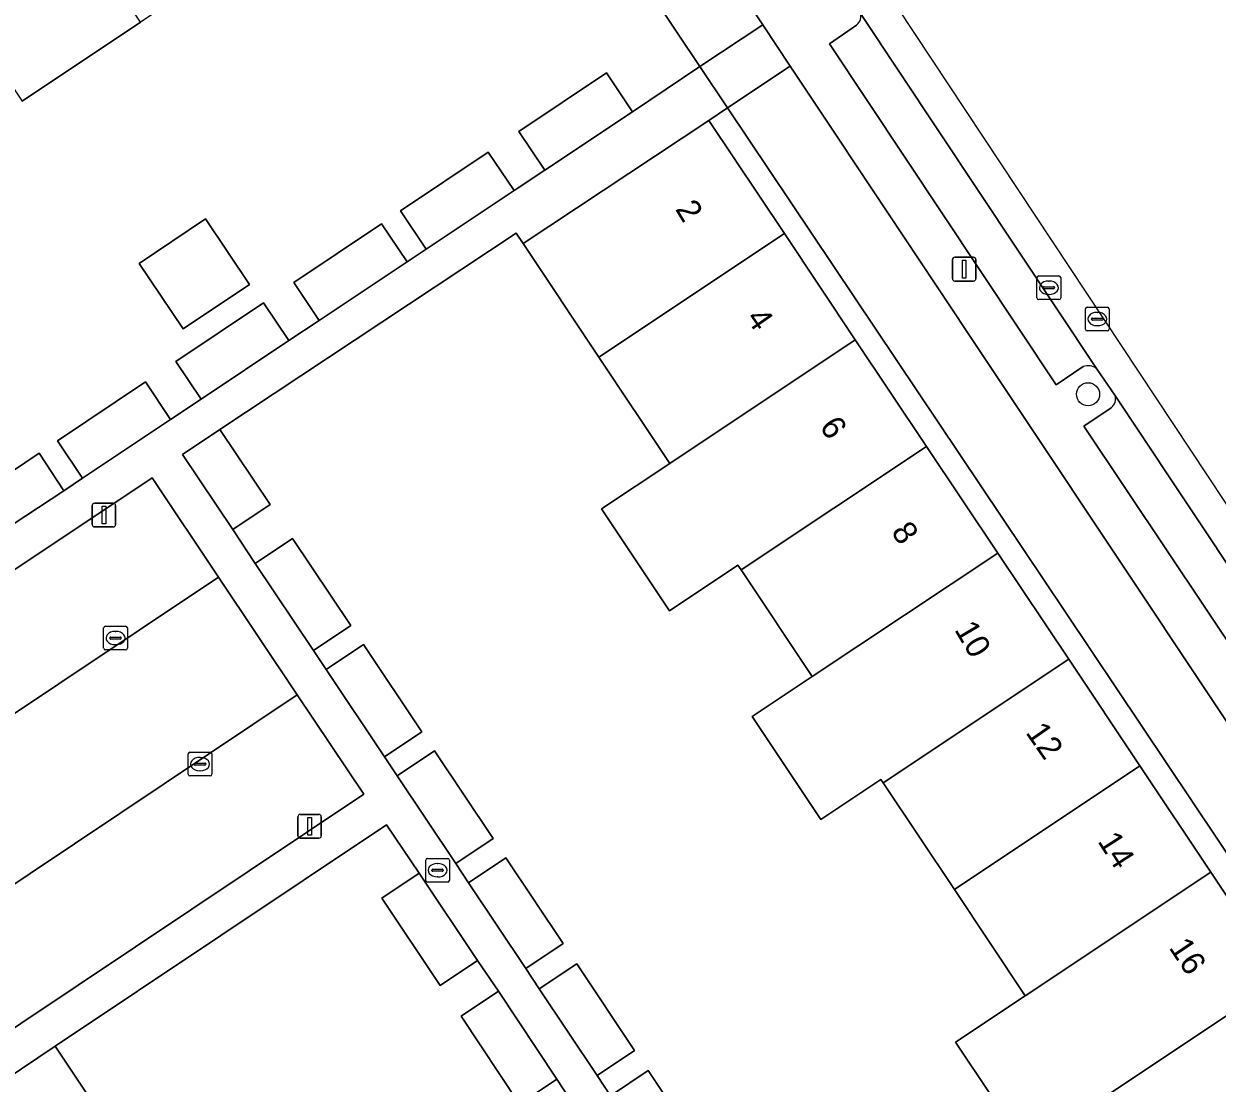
# Model space of a CAD drawing. Extents: x 158352 to 159489, y 383828 to 384603.
# Drawn here: x 158853 to 158903.3, y 384412.1 to 384456.8 of the extents above; entities that cross this region are included whole.
import ezdxf

# ---------------------------------------------------------------- set-up
doc = ezdxf.new("R2010")
doc.units = 0
for name, color, linetype in [('IMGEO_Boom', 7, 'Continuous'), ('IMGEO_Erf', 7, 'Continuous'), ('IMGEO_Kolk', 7, 'Continuous'), ('IMGEO_Lichtmast', 7, 'Continuous'), ('IMGEO_Pand', 7, 'Continuous'), ('IMGEO_Pand_nummerreeks', 7, 'Continuous'), ('IMGEO_Parkeervlak_open', 7, 'Continuous'), ('IMGEO_Rijbaan_lokaal_gesloten', 7, 'Continuous'), ('IMGEO_Rijbaan_lokaal_open', 7, 'Continuous'), ('IMGEO_Rioolput', 7, 'Continuous'), ('IMGEO_Voetpad_open', 7, 'Continuous')]:
    doc.layers.add(name, color=color, linetype=linetype)

msp = doc.modelspace()

# ---------------------------------------------------------------- linework, layer by layer
at = {"layer": 'IMGEO_Boom'}
msp.add_circle((158897.897, 384441.16), 0.489, dxfattribs=at)
at = {"layer": 'IMGEO_Erf'}
for points in [[(158871.439, 384475.884), (158869.53, 384478.817), (158866.797, 384476.999), (158881.542, 384454.976), (158884.184, 384456.734)], [(158899.598, 384433.573), (158885.345, 384454.99), (158882.708, 384453.235), (158896.943, 384431.973), (158958.047, 384340.708), (158960.345, 384342.297)], [(158857.909, 384446.679), (158860.705, 384448.554), (158862.558, 384445.789), (158859.762, 384443.914)]]:
    msp.add_lwpolyline(points, close=True, dxfattribs=at)
for points in [[(158849.97, 384436.184), (158853.689, 384438.677), (158854.728, 384437.092), (158855.524, 384437.619), (158854.466, 384439.198), (158858.167, 384441.679), (158859.227, 384440.097), (158860.515, 384440.96), (158859.454, 384442.542), (158863.15, 384445.02), (158864.218, 384443.427), (158865.492, 384444.275), (158864.421, 384445.872), (158868.117, 384448.35), (158869.195, 384446.742), (158870.003, 384447.28), (158868.923, 384448.89), (158872.619, 384451.368), (158873.706, 384449.747), (158874.996, 384450.606), (158873.906, 384452.231), (158877.603, 384454.709), (158878.7, 384453.073), (158881.542, 384454.976), (158866.797, 384476.999)], [(158848.053, 384460.87), (158853.047, 384464.192), (158857.548, 384467.185), (158862.533, 384470.501), (158867.746, 384473.968), (158872.617, 384466.647), (158872.513, 384466.577), (158874.416, 384463.732), (158869.334, 384460.333), (158869.095, 384460.69), (158864.119, 384457.362), (158862.455, 384459.85), (158857.962, 384456.845), (158852.977, 384453.51)], [(158958.047, 384340.708), (158896.943, 384431.973), (158882.708, 384453.235), (158881.915, 384452.704), (158885.098, 384447.937), (158888.089, 384443.457), (158891.089, 384438.962), (158894.09, 384434.468), (158897.081, 384429.988), (158900.082, 384425.492), (158903.072, 384421.013), (158906.071, 384416.517), (158909.059, 384412.037)], [(158895.312, 384409.35), (158892.313, 384413.844), (158895.254, 384415.804), (158892.264, 384420.284), (158889.263, 384424.78), (158889.165, 384424.926), (158886.635, 384423.238), (158883.741, 384427.573), (158886.273, 384429.26), (158883.272, 384433.755), (158883.137, 384433.958), (158880.26, 384432.037), (158877.396, 384436.329), (158880.272, 384438.249), (158877.282, 384442.729), (158874.09, 384447.51), (158873.799, 384447.946), (158861.31, 384439.679), (158863.428, 384436.513), (158861.849, 384435.456), (158862.793, 384434.029), (158864.373, 384435.085), (158866.83, 384431.412), (158865.251, 384430.356), (158865.783, 384429.557), (158867.363, 384430.613), (158869.819, 384426.934), (158868.239, 384425.879), (158868.777, 384425.077), (158870.356, 384426.129), (158872.827, 384422.43), (158871.247, 384421.375), (158871.788, 384420.567), (158873.366, 384421.619), (158875.777, 384418.007), (158874.196, 384416.953), (158874.77, 384416.094), (158876.351, 384417.147), (158878.786, 384413.498), (158877.203, 384412.443), (158877.767, 384411.592), (158879.351, 384412.652), (158881.773, 384409.023)], [(158876.048, 384411.482), (158875.511, 384412.288), (158873.932, 384411.231), (158871.473, 384414.946), (158873.052, 384416.003), (158872.17, 384417.289), (158870.591, 384416.233), (158868.129, 384419.915), (158869.709, 384420.971), (158868.332, 384423.007), (158854.372, 384413.675), (158857.87, 384408.431)]]:
    msp.add_lwpolyline(points, dxfattribs=at)
at = {"layer": 'IMGEO_Kolk'}
for p, q in [((158895.745, 384445.227), (158895.745, 384446.079)), ((158895.82, 384446.153), (158896.672, 384446.153)), ((158896.746, 384446.079), (158896.746, 384445.227)), ((158896.004, 384445.647), (158896.004, 384445.659)), ((158896.442, 384445.61), (158896.044, 384445.61)), ((158896.047, 384445.696), (158896.445, 384445.696)), ((158896.233, 384445.933), (158896.258, 384445.933)), ((158896.488, 384445.659), (158896.488, 384445.647)), ((158896.672, 384445.153), (158895.82, 384445.153)), ((158896.256, 384445.373), (158896.231, 384445.373)), ((158856.409, 384430.46), (158856.409, 384431.312)), ((158856.484, 384431.386), (158857.336, 384431.386)), ((158856.897, 384431.166), (158856.922, 384431.166)), ((158857.41, 384431.312), (158857.41, 384430.46)), ((158856.668, 384430.88), (158856.668, 384430.892)), ((158857.106, 384430.843), (158856.708, 384430.843)), ((158856.711, 384430.929), (158857.109, 384430.929)), ((158856.92, 384430.606), (158856.895, 384430.606)), ((158857.152, 384430.892), (158857.152, 384430.88)), ((158857.336, 384430.386), (158856.484, 384430.386)), ((158859.972, 384425.147), (158859.972, 384425.999)), ((158860.047, 384426.073), (158860.899, 384426.073)), ((158860.973, 384425.999), (158860.973, 384425.147)), ((158860.231, 384425.567), (158860.231, 384425.579)), ((158860.669, 384425.53), (158860.271, 384425.53)), ((158860.274, 384425.616), (158860.672, 384425.616)), ((158860.46, 384425.853), (158860.485, 384425.853)), ((158860.715, 384425.579), (158860.715, 384425.567)), ((158860.899, 384425.073), (158860.047, 384425.073)), ((158860.483, 384425.293), (158860.458, 384425.293)), ((158869.981, 384420.671), (158869.981, 384421.523)), ((158870.056, 384421.597), (158870.908, 384421.597)), ((158870.982, 384421.523), (158870.982, 384420.671)), ((158870.24, 384421.091), (158870.24, 384421.103)), ((158870.678, 384421.054), (158870.28, 384421.054)), ((158870.283, 384421.14), (158870.681, 384421.14)), ((158870.469, 384421.377), (158870.494, 384421.377)), ((158870.724, 384421.103), (158870.724, 384421.091)), ((158870.908, 384420.597), (158870.056, 384420.597)), ((158870.492, 384420.817), (158870.467, 384420.817))]:
    msp.add_line(p, q, dxfattribs=at)
for points in [[(158895.745, 384445.227), (158895.745, 384446.079)], [(158895.82, 384446.153), (158896.672, 384446.153)], [(158896.746, 384446.079), (158896.746, 384445.227)], [(158896.672, 384445.153), (158895.82, 384445.153)], [(158856.409, 384430.46), (158856.409, 384431.312)], [(158856.484, 384431.386), (158857.336, 384431.386)], [(158857.41, 384431.312), (158857.41, 384430.46)], [(158857.336, 384430.386), (158856.484, 384430.386)], [(158859.972, 384425.147), (158859.972, 384425.999)], [(158860.047, 384426.073), (158860.899, 384426.073)], [(158860.973, 384425.999), (158860.973, 384425.147)], [(158860.899, 384425.073), (158860.047, 384425.073)], [(158869.981, 384420.671), (158869.981, 384421.523)], [(158870.056, 384421.597), (158870.908, 384421.597)], [(158870.982, 384421.523), (158870.982, 384420.671)], [(158870.908, 384420.597), (158870.056, 384420.597)]]:
    msp.add_lwpolyline(points, dxfattribs=at)
for centre, radius, start, end in [((158895.822, 384446.077), 0.0765, 91.552, 178.448), ((158895.822, 384446.077), 0.0765, 91.552, 178.448), ((158896.67, 384446.077), 0.0765, 1.552, 88.448), ((158896.67, 384446.077), 0.0765, 1.552, 88.448), ((158896.044, 384445.656), 0.0403, 85.8775, 175.7526), ((158896.041, 384445.646), 0.0366, 178.938, 274.7102), ((158896.445, 384445.653), 0.043, 264.8664, 352.4533), ((158896.449, 384445.658), 0.0386, 1.7309, 96.639), ((158895.822, 384445.229), 0.0765, 181.552, 268.448), ((158895.822, 384445.229), 0.0765, 181.552, 268.448), ((158896.67, 384445.229), 0.0765, 271.552, 358.448), ((158896.67, 384445.229), 0.0765, 271.552, 358.448), ((158856.486, 384431.31), 0.0765, 91.552, 178.448), ((158856.486, 384431.31), 0.0765, 91.552, 178.448), ((158857.334, 384431.31), 0.0765, 1.552, 88.448), ((158857.334, 384431.31), 0.0765, 1.552, 88.448), ((158856.486, 384430.462), 0.0765, 181.552, 268.448), ((158856.486, 384430.462), 0.0765, 181.552, 268.448), ((158856.708, 384430.889), 0.0403, 85.8775, 175.7526), ((158856.705, 384430.879), 0.0366, 178.938, 274.7102), ((158857.109, 384430.886), 0.043, 264.8664, 352.4533), ((158857.113, 384430.891), 0.0386, 1.7309, 96.639), ((158857.334, 384430.462), 0.0765, 271.552, 358.448), ((158857.334, 384430.462), 0.0765, 271.552, 358.448), ((158860.049, 384425.997), 0.0765, 91.552, 178.448), ((158860.049, 384425.997), 0.0765, 91.552, 178.448), ((158860.897, 384425.997), 0.0765, 1.552, 88.448), ((158860.897, 384425.997), 0.0765, 1.552, 88.448), ((158860.271, 384425.576), 0.0403, 85.8775, 175.7526), ((158860.268, 384425.566), 0.0366, 178.938, 274.7102), ((158860.672, 384425.573), 0.043, 264.8664, 352.4533), ((158860.676, 384425.578), 0.0386, 1.7309, 96.639), ((158860.049, 384425.149), 0.0765, 181.552, 268.448), ((158860.049, 384425.149), 0.0765, 181.552, 268.448), ((158860.897, 384425.149), 0.0765, 271.552, 358.448), ((158860.897, 384425.149), 0.0765, 271.552, 358.448), ((158870.058, 384421.521), 0.0765, 91.552, 178.448), ((158870.058, 384421.521), 0.0765, 91.552, 178.448), ((158870.906, 384421.521), 0.0765, 1.552, 88.448), ((158870.906, 384421.521), 0.0765, 1.552, 88.448), ((158870.28, 384421.1), 0.0403, 85.8775, 175.7526), ((158870.277, 384421.09), 0.0366, 178.938, 274.7102), ((158870.681, 384421.097), 0.043, 264.8664, 352.4533), ((158870.685, 384421.102), 0.0386, 1.7309, 96.639), ((158870.058, 384420.673), 0.0765, 181.552, 268.448), ((158870.058, 384420.673), 0.0765, 181.552, 268.448), ((158870.906, 384420.673), 0.0765, 271.552, 358.448), ((158870.906, 384420.673), 0.0765, 271.552, 358.448)]:
    msp.add_arc(centre, radius, start, end, dxfattribs=at)
for centre, major_axis, ratio, start_param, end_param in [((158896.232, 384445.653), (-0.387, 0.002), 0.722429, 4.712389, 7.853982), ((158896.257, 384445.653), (-0.39, 0.002), 0.717154, 1.570796, 4.712389), ((158856.896, 384430.886), (-0.387, 0.002), 0.722429, 4.712389, 7.853982), ((158856.921, 384430.886), (-0.39, 0.002), 0.717154, 1.570796, 4.712389), ((158860.459, 384425.573), (-0.387, 0.002), 0.722429, 4.712389, 7.853982), ((158860.484, 384425.573), (-0.39, 0.002), 0.717154, 1.570796, 4.712389), ((158870.468, 384421.097), (-0.387, 0.002), 0.722429, 4.712389, 7.853982), ((158870.493, 384421.097), (-0.39, 0.002), 0.717154, 1.570796, 4.712389)]:
    msp.add_ellipse(centre, major_axis=major_axis, ratio=ratio, start_param=start_param, end_param=end_param, dxfattribs=at)
at = {"layer": 'IMGEO_Lichtmast'}
for p, q in [((158892.183, 384446.036), (158892.183, 384446.836)), ((158892.183, 384446.836), (158892.183, 384446.036)), ((158892.283, 384446.936), (158893.073, 384446.936)), ((158893.073, 384446.936), (158892.283, 384446.936)), ((158893.173, 384446.836), (158893.173, 384446.036)), ((158893.173, 384446.036), (158893.173, 384446.836)), ((158893.073, 384445.936), (158892.283, 384445.936)), ((158892.283, 384445.936), (158893.073, 384445.936)), ((158856.024, 384436.571), (158856.814, 384436.571)), ((158856.814, 384436.571), (158856.024, 384436.571)), ((158855.924, 384435.671), (158855.924, 384436.471)), ((158855.924, 384436.471), (158855.924, 384435.671)), ((158856.914, 384436.471), (158856.914, 384435.671)), ((158856.914, 384435.671), (158856.914, 384436.471)), ((158856.814, 384435.571), (158856.024, 384435.571)), ((158856.024, 384435.571), (158856.814, 384435.571)), ((158864.692, 384423.45), (158865.482, 384423.45)), ((158865.482, 384423.45), (158864.692, 384423.45)), ((158864.592, 384422.55), (158864.592, 384423.35)), ((158864.592, 384423.35), (158864.592, 384422.55)), ((158865.582, 384423.35), (158865.582, 384422.55)), ((158865.582, 384422.55), (158865.582, 384423.35)), ((158865.482, 384422.45), (158864.692, 384422.45)), ((158864.692, 384422.45), (158865.482, 384422.45))]:
    msp.add_line(p, q, dxfattribs=at)
for points in [[(158892.603, 384446.811), (158892.753, 384446.811), (158892.753, 384446.061), (158892.603, 384446.061), (158892.603, 384446.811)], [(158856.344, 384436.446), (158856.494, 384436.446), (158856.494, 384435.696), (158856.344, 384435.696), (158856.344, 384436.446)], [(158865.012, 384423.325), (158865.162, 384423.325), (158865.162, 384422.575), (158865.012, 384422.575), (158865.012, 384423.325)]]:
    msp.add_lwpolyline(points, dxfattribs=at)
for centre, start, end in [((158892.283, 384446.836), 90, 180), ((158892.283, 384446.836), 90, 180), ((158893.073, 384446.836), 0, 90), ((158893.073, 384446.836), 360, 90), ((158892.283, 384446.036), 180, 270), ((158892.283, 384446.036), 180, 270), ((158893.073, 384446.036), 270, 0), ((158893.073, 384446.036), 270, 0), ((158856.024, 384436.471), 90, 180), ((158856.024, 384436.471), 90, 180), ((158856.814, 384436.471), 0, 90), ((158856.814, 384436.471), 360, 90), ((158856.024, 384435.671), 180, 270), ((158856.024, 384435.671), 180, 270), ((158856.814, 384435.671), 270, 0), ((158856.814, 384435.671), 270, 0), ((158864.692, 384423.35), 90, 180), ((158864.692, 384423.35), 90, 180), ((158865.482, 384423.35), 0, 90), ((158865.482, 384423.35), 360, 90), ((158864.692, 384422.55), 180, 270), ((158864.692, 384422.55), 180, 270), ((158865.482, 384422.55), 270, 0), ((158865.482, 384422.55), 270, 0)]:
    msp.add_arc(centre, 0.1, start, end, dxfattribs=at)
at = {"layer": 'IMGEO_Pand'}
for points in [[(158853.047, 384464.192), (158848.053, 384460.87), (158852.977, 384453.51), (158857.962, 384456.845)], [(158874.996, 384450.606), (158878.7, 384453.073), (158877.603, 384454.709), (158873.906, 384452.231)], [(158885.098, 384447.937), (158881.915, 384452.704), (158874.09, 384447.51), (158877.282, 384442.729)], [(158870.003, 384447.28), (158873.706, 384449.747), (158872.619, 384451.368), (158868.923, 384448.89)], [(158857.909, 384446.679), (158859.762, 384443.914), (158862.558, 384445.789), (158860.705, 384448.554)], [(158865.492, 384444.275), (158869.195, 384446.742), (158868.117, 384448.35), (158864.421, 384445.872)], [(158885.098, 384447.937), (158877.282, 384442.729), (158880.272, 384438.249), (158888.089, 384443.457)], [(158864.218, 384443.427), (158863.15, 384445.02), (158859.454, 384442.542), (158860.515, 384440.96)], [(158891.089, 384438.962), (158888.089, 384443.457), (158880.272, 384438.249), (158877.396, 384436.329), (158880.26, 384432.037), (158883.137, 384433.958), (158883.272, 384433.755)], [(158855.524, 384437.619), (158859.227, 384440.097), (158858.167, 384441.679), (158854.466, 384439.198)], [(158861.31, 384439.679), (158859.731, 384438.622), (158861.849, 384435.456), (158863.428, 384436.513)], [(158850.984, 384434.637), (158854.728, 384437.092), (158853.689, 384438.677), (158849.97, 384436.184)], [(158891.089, 384438.962), (158883.272, 384433.755), (158886.273, 384429.26), (158894.09, 384434.468)], [(158865.251, 384430.356), (158866.83, 384431.412), (158864.373, 384435.085), (158862.793, 384434.029)], [(158897.081, 384429.988), (158894.09, 384434.468), (158886.273, 384429.26), (158883.741, 384427.573), (158886.635, 384423.238), (158889.165, 384424.926), (158889.263, 384424.78)], [(158865.783, 384429.557), (158868.239, 384425.879), (158869.819, 384426.934), (158867.363, 384430.613)], [(158900.082, 384425.492), (158897.081, 384429.988), (158889.263, 384424.78), (158892.264, 384420.284)], [(158868.777, 384425.077), (158871.247, 384421.375), (158872.827, 384422.43), (158870.356, 384426.129)], [(158900.082, 384425.492), (158892.264, 384420.284), (158895.254, 384415.804), (158903.072, 384421.013)], [(158871.788, 384420.567), (158874.196, 384416.953), (158875.777, 384418.007), (158873.366, 384421.619)], [(158869.709, 384420.971), (158868.129, 384419.915), (158870.591, 384416.233), (158872.17, 384417.289)], [(158906.071, 384416.517), (158903.072, 384421.013), (158895.254, 384415.804), (158892.313, 384413.844), (158895.312, 384409.35), (158898.254, 384411.31)], [(158877.203, 384412.443), (158878.786, 384413.498), (158876.351, 384417.147), (158874.77, 384416.094)], [(158906.071, 384416.517), (158898.254, 384411.31), (158901.244, 384406.831), (158909.059, 384412.037)], [(158873.052, 384416.003), (158871.473, 384414.946), (158873.932, 384411.231), (158875.511, 384412.288)], [(158850.034, 384403.207), (158857.87, 384408.431), (158854.372, 384413.675), (158850.051, 384410.791), (158846.537, 384408.445)], [(158880.196, 384407.966), (158881.773, 384409.023), (158879.351, 384412.652), (158877.767, 384411.592)]]:
    msp.add_lwpolyline(points, close=True, dxfattribs=at)
at = {"layer": 'IMGEO_Parkeervlak_open'}
for points in [[(158898.259, 384442.243), (158888.28, 384457.252)], [(158888.14, 384456.722), (158886.996, 384455.934), (158896.557, 384441.558), (158897.695, 384442.327)], [(158906.139, 384430.429), (158902.775, 384435.489), (158899.028, 384441.124)], [(158898.875, 384440.591), (158897.72, 384439.815), (158901.234, 384434.56), (158904.435, 384429.772), (158905.595, 384430.523)]]:
    msp.add_lwpolyline(points, dxfattribs=at)
for points in [[(158844.433, 384422.221), (158861.25, 384433.452), (158858.457, 384437.632), (158841.609, 384426.417)], [(158864.569, 384428.486), (158847.695, 384417.215), (158850.486, 384413.028), (158867.368, 384424.298)]]:
    msp.add_lwpolyline(points, close=True, dxfattribs=at)
for centre, radius, start, end in [((158887.878, 384457.075), 0.439, 306.5806, 23.8259), ((158897.904, 384441.792), 0.574, 51.7513, 111.3064), ((158898.584, 384440.963), 0.472, 308.0531, 19.9142)]:
    msp.add_arc(centre, radius, start, end, dxfattribs=at)
at = {"layer": 'IMGEO_Rijbaan_lokaal_gesloten'}
for points in [[(158875.263, 384479.53), (158874.302, 384478.867), (158874.82, 384477.468), (158884.4, 384463.1), (158888.28, 384457.252), (158898.259, 384442.243), (158899.028, 384441.124), (158902.775, 384435.489), (158906.139, 384430.429), (158906.908, 384429.304), (158920.007, 384409.58), (158920.763, 384408.459), (158933.684, 384389.073), (158934.462, 384387.903), (158948.108, 384367.417), (158948.862, 384366.323), (158955.957, 384355.688), (158956.746, 384354.542), (158963.568, 384344.252), (158966.627, 384339.706), (158967.515, 384338.34), (158974.141, 384328.364)], [(158974.618, 384328.235), (158976.716, 384325.103), (158977.265, 384325.504), (158977.265, 384325.504), (158875.263, 384479.53)]]:
    msp.add_lwpolyline(points, dxfattribs=at)
at = {"layer": 'IMGEO_Rijbaan_lokaal_open'}
msp.add_lwpolyline([(158847.487, 384417.528), (158847.695, 384417.215), (158864.569, 384428.486), (158861.25, 384433.452), (158844.433, 384422.221), (158844.639, 384421.916)], dxfattribs=at)
at = {"layer": 'IMGEO_Rioolput'}
for p, q in [((158897.787, 384443.907), (158897.787, 384444.759)), ((158897.862, 384444.833), (158898.714, 384444.833)), ((158898.275, 384444.613), (158898.3, 384444.613)), ((158898.788, 384444.759), (158898.788, 384443.907)), ((158898.046, 384444.327), (158898.046, 384444.339)), ((158898.484, 384444.29), (158898.086, 384444.29)), ((158898.089, 384444.376), (158898.487, 384444.376)), ((158898.298, 384444.053), (158898.273, 384444.053)), ((158898.53, 384444.339), (158898.53, 384444.327)), ((158898.714, 384443.833), (158897.862, 384443.833))]:
    msp.add_line(p, q, dxfattribs=at)
for points in [[(158897.787, 384443.907), (158897.787, 384444.759)], [(158897.862, 384444.833), (158898.714, 384444.833)], [(158898.788, 384444.759), (158898.788, 384443.907)], [(158898.714, 384443.833), (158897.862, 384443.833)]]:
    msp.add_lwpolyline(points, dxfattribs=at)
for centre, radius, start, end in [((158897.864, 384444.757), 0.0765, 91.552, 178.448), ((158897.864, 384444.757), 0.0765, 91.552, 178.448), ((158898.712, 384444.757), 0.0765, 1.552, 88.448), ((158898.712, 384444.757), 0.0765, 1.552, 88.448), ((158898.086, 384444.336), 0.0403, 85.8775, 175.7526), ((158898.083, 384444.326), 0.0366, 178.938, 274.7102), ((158898.487, 384444.333), 0.043, 264.8664, 352.4533), ((158898.491, 384444.338), 0.0386, 1.7309, 96.639), ((158897.864, 384443.909), 0.0765, 181.552, 268.448), ((158897.864, 384443.909), 0.0765, 181.552, 268.448), ((158898.712, 384443.909), 0.0765, 271.552, 358.448), ((158898.712, 384443.909), 0.0765, 271.552, 358.448)]:
    msp.add_arc(centre, radius, start, end, dxfattribs=at)
for centre, major_axis, ratio, start_param, end_param in [((158898.274, 384444.333), (-0.387, 0.002), 0.722429, 4.712389, 7.853982), ((158898.299, 384444.333), (-0.39, 0.002), 0.717154, 1.570796, 4.712389)]:
    msp.add_ellipse(centre, major_axis=major_axis, ratio=ratio, start_param=start_param, end_param=end_param, dxfattribs=at)
at = {"layer": 'IMGEO_Voetpad_open'}
for points in [[(158883.84, 384463.169), (158882.723, 384462.395), (158872.711, 384477.381), (158871.439, 384475.884), (158884.184, 384456.734), (158885.345, 384454.99), (158899.598, 384433.573), (158960.345, 384342.297), (158973.377, 384322.58), (158974.997, 384323.628), (158974.847, 384323.853), (158976.716, 384325.103), (158974.618, 384328.235)], [(158897.695, 384442.327), (158896.557, 384441.558), (158886.996, 384455.934), (158888.14, 384456.722)], [(158877.767, 384411.592), (158877.203, 384412.443), (158874.77, 384416.094), (158874.196, 384416.953), (158871.788, 384420.567), (158871.247, 384421.375), (158868.777, 384425.077), (158868.239, 384425.879), (158865.783, 384429.557), (158865.251, 384430.356), (158862.793, 384434.029), (158861.849, 384435.456), (158859.731, 384438.622), (158861.31, 384439.679), (158873.799, 384447.946), (158874.09, 384447.51), (158881.915, 384452.704), (158882.708, 384453.235), (158881.542, 384454.976), (158878.7, 384453.073), (158874.996, 384450.606), (158873.706, 384449.747), (158870.003, 384447.28), (158869.195, 384446.742), (158865.492, 384444.275), (158864.218, 384443.427), (158860.515, 384440.96), (158859.227, 384440.097), (158855.524, 384437.619), (158854.728, 384437.092), (158850.984, 384434.637)], [(158899.028, 384441.124), (158898.259, 384442.243)], [(158905.595, 384430.523), (158904.435, 384429.772), (158901.234, 384434.56), (158897.72, 384439.815), (158898.875, 384440.591)], [(158844.639, 384421.916), (158844.433, 384422.221), (158841.609, 384426.417), (158858.457, 384437.632), (158861.25, 384433.452), (158864.569, 384428.486), (158867.368, 384424.298), (158850.486, 384413.028), (158847.695, 384417.215), (158847.487, 384417.528)], [(158846.842, 384417.659), (158843.489, 384415.541), (158844.174, 384414.505), (158846.541, 384416.082), (158850.051, 384410.791), (158854.372, 384413.675), (158868.332, 384423.007), (158869.709, 384420.971), (158872.17, 384417.289), (158873.052, 384416.003), (158875.511, 384412.288), (158876.048, 384411.482)]]:
    msp.add_lwpolyline(points, dxfattribs=at)
msp.add_lwpolyline([(158884.184, 384456.734), (158881.542, 384454.976), (158882.708, 384453.235), (158885.345, 384454.99)], close=True, dxfattribs=at)
for centre, radius, start, end in [((158887.878, 384457.075), 0.439, 306.5806, 23.8259), ((158897.904, 384441.792), 0.574, 51.7513, 111.3064), ((158898.584, 384440.963), 0.472, 308.0531, 19.9142)]:
    msp.add_arc(centre, radius, start, end, dxfattribs=at)

# ---------------------------------------------------------------- texts
at = {"layer": 'IMGEO_Pand_nummerreeks'}
for s, rotation, p in [('2', 301.3821, (158880.478, 384448.969)), ('4', 304.7805, (158883.456, 384444.367)), ('6', 304.5262, (158886.554, 384439.793)), ('8', 304.1059, (158889.571, 384435.357)), ('10', 300.59, (158892.244, 384431.242)), ('12', 304.8159, (158895.24, 384426.901)), ('14', 302.6964, (158898.276, 384422.321)), ('16', 303.8272, (158901.278, 384417.834))]:
    msp.add_text(s, height=1, rotation=rotation, dxfattribs=at).set_placement(p)

doc.saveas('drawing.dxf')
